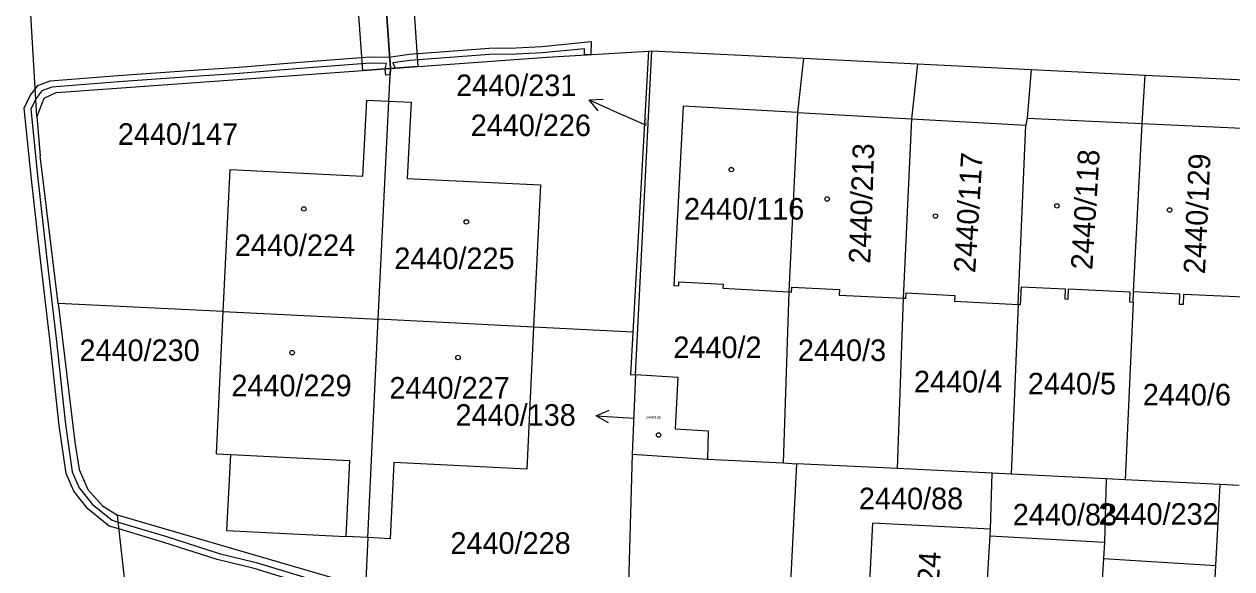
# Model space of a CAD drawing. Extents: x -755819 to -753140, y -1169796 to -1166000.
# Drawn here: x -755355.4 to -755260.2, y -1168237.4 to -1168194.5 of the extents above; entities that cross this region are included whole.
import ezdxf

# ---------------------------------------------------------------- set-up
doc = ezdxf.new("R2010")
doc.units = 0
for name, color, linetype in [('Vrstva 1', 7, 'Continuous'), ('Vrstva 16', 7, 'Continuous'), ('Vrstva 18', 7, 'Continuous'), ('Vrstva 19', 7, 'Continuous'), ('Vrstva 25', 7, 'Continuous'), ('Vrstva 27', 7, 'Continuous'), ('Vrstva 4', 7, 'Continuous')]:
    doc.layers.add(name, color=color, linetype=linetype)

msp = doc.modelspace()

# ---------------------------------------------------------------- linework, layer by layer
at = {"layer": 'Vrstva 1'}
for p, q in [((-755354.43, -1168201.81), (-755355.26, -1168187.16)), ((-755326.53, -1168198.02), (-755314.2, -1168197.14)), ((-755314.2, -1168197.14), (-755306.2, -1168196.65)), ((-755306.2, -1168196.65), (-755307.42, -1168218.8)), ((-755307.23, -1168222.13), (-755305.92, -1168196.63)), ((-755306.2, -1168196.65), (-755305.92, -1168196.63)), ((-755305.92, -1168196.63), (-755293.96, -1168197.22)), ((-755352.88, -1168199.91), (-755326.53, -1168198.02)), ((-755326.66, -1168200.6), (-755326.53, -1168198.02)), ((-755293.96, -1168197.22), (-755294.44, -1168201.49)), ((-755293.96, -1168197.22), (-755284.98, -1168197.66)), ((-755284.98, -1168197.66), (-755285.45, -1168201.99)), ((-755284.98, -1168197.66), (-755276.01, -1168198.1)), ((-755276.01, -1168198.1), (-755276.35, -1168201.93)), ((-755276.01, -1168198.1), (-755267.04, -1168198.54)), ((-755267.26, -1168202.36), (-755267.04, -1168198.54)), ((-755267.04, -1168198.54), (-755258.07, -1168198.98)), ((-755352.88, -1168199.91), (-755353.87, -1168200.38)), ((-755353.87, -1168200.38), (-755354.43, -1168201.81)), ((-755328.71, -1168206.5), (-755328.41, -1168200.51)), ((-755328.41, -1168200.51), (-755326.66, -1168200.6)), ((-755327.51, -1168217.78), (-755326.66, -1168200.6)), ((-755326.66, -1168200.6), (-755324.91, -1168200.69)), ((-755324.91, -1168200.69), (-755325.21, -1168206.68)), ((-755354.43, -1168201.81), (-755354.16, -1168204.91)), ((-755303.45, -1168200.99), (-755304.19, -1168215.13)), ((-755294.44, -1168201.49), (-755303.45, -1168200.99)), ((-755294.44, -1168201.49), (-755295.12, -1168215.63)), ((-755276.35, -1168201.93), (-755276.45, -1168202.48)), ((-755285.45, -1168201.99), (-755286.11, -1168216.12)), ((-755277.06, -1168216.62), (-755276.45, -1168202.48)), ((-755267.95, -1168215.63), (-755267.26, -1168202.36)), ((-755352.75, -1168216.54), (-755354.16, -1168204.91)), ((-755339.72, -1168217.18), (-755339.19, -1168205.98)), ((-755339.19, -1168205.98), (-755328.71, -1168206.5)), ((-755325.21, -1168206.68), (-755314.72, -1168207.2)), ((-755314.72, -1168207.2), (-755315.26, -1168218.4)), ((-755304.19, -1168215.13), (-755303.81, -1168215.15)), ((-755303.81, -1168215.15), (-755303.79, -1168214.82)), ((-755303.79, -1168214.82), (-755300.3, -1168215.01)), ((-755300.3, -1168215.01), (-755300.32, -1168215.34)), ((-755294.92, -1168215.64), (-755294.9, -1168215.24)), ((-755294.9, -1168215.24), (-755291.13, -1168215.43)), ((-755276.86, -1168216.63), (-755276.79, -1168215.22)), ((-755276.79, -1168215.22), (-755273.33, -1168215.39)), ((-755300.32, -1168215.34), (-755295.12, -1168215.63)), ((-755295.12, -1168215.63), (-755295.58, -1168229.08)), ((-755295.12, -1168215.63), (-755294.92, -1168215.64)), ((-755291.13, -1168215.43), (-755291.15, -1168215.88)), ((-755291.15, -1168215.88), (-755286.11, -1168216.12)), ((-755286.11, -1168216.12), (-755286.59, -1168229.53)), ((-755286.11, -1168216.12), (-755285.91, -1168216.13)), ((-755285.91, -1168216.13), (-755285.89, -1168215.69)), ((-755285.89, -1168215.69), (-755282.04, -1168215.9)), ((-755282.04, -1168215.9), (-755282.06, -1168216.35)), ((-755273.33, -1168215.39), (-755273.37, -1168216.18)), ((-755273.37, -1168216.18), (-755273.11, -1168216.19)), ((-755273.11, -1168216.19), (-755273.07, -1168215.39)), ((-755273.07, -1168215.39), (-755268.24, -1168215.62)), ((-755268.24, -1168215.62), (-755268.28, -1168216.42)), ((-755267.99, -1168216.43), (-755267.95, -1168215.63)), ((-755264.29, -1168215.81), (-755267.95, -1168215.63)), ((-755264.32, -1168216.61), (-755264.29, -1168215.81)), ((-755264.01, -1168215.82), (-755264.04, -1168216.62)), ((-755259.23, -1168216.05), (-755264.01, -1168215.82)), ((-755339.72, -1168217.18), (-755352.75, -1168216.54)), ((-755352.75, -1168216.54), (-755351.43, -1168227.46)), ((-755282.06, -1168216.35), (-755277.06, -1168216.62)), ((-755277.06, -1168216.62), (-755277.6, -1168229.98)), ((-755277.06, -1168216.62), (-755276.86, -1168216.63)), ((-755267.99, -1168216.43), (-755268.61, -1168230.43)), ((-755268.28, -1168216.42), (-755267.99, -1168216.43)), ((-755264.04, -1168216.62), (-755264.32, -1168216.61)), ((-755340.26, -1168228.38), (-755339.72, -1168217.18)), ((-755339.72, -1168217.18), (-755327.51, -1168217.78)), ((-755328.32, -1168234.98), (-755327.51, -1168217.78)), ((-755315.26, -1168218.4), (-755327.51, -1168217.78)), ((-755315.26, -1168218.4), (-755315.79, -1168229.6)), ((-755307.42, -1168218.8), (-755315.26, -1168218.4)), ((-755307.42, -1168218.8), (-755307.6, -1168222.16)), ((-755307.6, -1168222.16), (-755307.23, -1168222.13)), ((-755307.23, -1168222.13), (-755307.48, -1168228.42)), ((-755307.23, -1168222.13), (-755303.87, -1168222.33)), ((-755303.87, -1168222.33), (-755304.08, -1168226.42)), ((-755304.08, -1168226.42), (-755301.48, -1168226.56)), ((-755301.48, -1168226.56), (-755301.53, -1168228.79)), ((-755351.43, -1168227.46), (-755351.08, -1168229.61)), ((-755340.26, -1168228.38), (-755339.16, -1168228.43)), ((-755339.16, -1168228.43), (-755339.46, -1168234.43)), ((-755307.48, -1168228.42), (-755307.94, -1168244.9)), ((-755307.48, -1168228.42), (-755301.53, -1168228.79)), ((-755326.27, -1168229.07), (-755326.57, -1168235.07)), ((-755315.79, -1168229.6), (-755326.27, -1168229.07)), ((-755301.53, -1168228.79), (-755295.58, -1168229.08)), ((-755295.58, -1168229.08), (-755294.53, -1168229.17)), ((-755294.53, -1168229.17), (-755295.49, -1168248.57)), ((-755286.59, -1168229.53), (-755294.53, -1168229.17)), ((-755279.1, -1168229.9), (-755286.59, -1168229.53)), ((-755351.08, -1168229.61), (-755350.39, -1168231.19)), ((-755279.23, -1168234.31), (-755279.1, -1168229.9)), ((-755277.6, -1168229.98), (-755279.1, -1168229.9)), ((-755270.11, -1168230.35), (-755277.6, -1168229.98)), ((-755270.11, -1168230.35), (-755270.23, -1168235.33)), ((-755268.61, -1168230.43), (-755270.11, -1168230.35)), ((-755261.12, -1168230.8), (-755268.61, -1168230.43)), ((-755350.39, -1168231.19), (-755349.25, -1168232.47)), ((-755261.46, -1168237.18), (-755261.12, -1168230.8)), ((-755259.62, -1168230.87), (-755261.12, -1168230.8)), ((-755349.25, -1168232.47), (-755348.07, -1168233.2)), ((-755328.5, -1168238.9), (-755348.07, -1168233.2)), ((-755346.65, -1168245.86), (-755348.07, -1168233.2)), ((-755288.54, -1168233.84), (-755289.18, -1168246.38)), ((-755279.23, -1168234.31), (-755288.54, -1168233.84)), ((-755339.46, -1168234.43), (-755330.07, -1168234.89)), ((-755328.32, -1168234.98), (-755330.07, -1168234.89)), ((-755328.32, -1168234.98), (-755328.5, -1168238.9)), ((-755326.57, -1168235.07), (-755328.32, -1168234.98)), ((-755280.05, -1168247.85), (-755279.26, -1168234.83)), ((-755279.26, -1168234.83), (-755279.23, -1168234.31)), ((-755270.23, -1168235.33), (-755270.31, -1168236.63)), ((-755270.31, -1168236.63), (-755271.08, -1168248.47)), ((-755270.31, -1168236.63), (-755261.46, -1168237.18)), ((-755261.51, -1168238.17), (-755261.46, -1168237.18))]:
    msp.add_line(p, q, dxfattribs=at)
at = {"layer": 'Vrstva 16'}
for p, q in [((-755310.881, -1168200.5), (-755308.14, -1168201.72)), ((-755306.36, -1168202.52), (-755308.14, -1168201.72)), ((-755310.314, -1168225.378), (-755307.32, -1168225.56))]:
    msp.add_line(p, q, dxfattribs=at)
for points in [[(-755310.17, -1168201.363), (-755310.881, -1168200.5), (-755309.764, -1168200.45)], [(-755309.347, -1168225.938), (-755310.314, -1168225.378), (-755309.286, -1168224.939)]]:
    msp.add_lwpolyline(points, dxfattribs=at)
at = {"layer": 'Vrstva 25'}
for centre in [(-755299.66, -1168205.99), (-755292.11, -1168208.31), (-755333.37, -1168209.09), (-755283.57, -1168209.65), (-755273.99, -1168208.85), (-755265.1, -1168209.17), (-755320.56, -1168210.11), (-755334.29, -1168220.41), (-755321.21, -1168220.79), (-755305.4, -1168226.9)]:
    msp.add_circle(centre, 0.175, dxfattribs=at)
at = {"layer": 'Vrstva 27'}
for p, q in [((-755328.73, -1168198.18), (-755329.51, -1168187.22)), ((-755326.53, -1168198.02), (-755327.31, -1168187.06)), ((-755327.31, -1168187.06), (-755326.53, -1168198.02)), ((-755325.15, -1168186.9), (-755324.37, -1168197.87)), ((-755314.61, -1168196.29), (-755310.71, -1168195.91)), ((-755310.71, -1168195.91), (-755310.73, -1168196.93)), ((-755334.01, -1168197.56), (-755328.16, -1168197.11)), ((-755328.16, -1168197.11), (-755326.66, -1168197.13)), ((-755326.66, -1168197.13), (-755325.06, -1168196.9)), ((-755325.06, -1168196.9), (-755318.75, -1168196.43)), ((-755318.73, -1168196.93), (-755325, -1168197.4)), ((-755318.75, -1168196.43), (-755316.64, -1168196.39)), ((-755316.62, -1168196.89), (-755318.73, -1168196.93)), ((-755316.64, -1168196.39), (-755314.61, -1168196.29)), ((-755314.57, -1168196.79), (-755316.62, -1168196.89)), ((-755311.23, -1168196.47), (-755314.57, -1168196.79)), ((-755311.23, -1168196.96), (-755311.23, -1168196.47)), ((-755310.73, -1168196.93), (-755311.23, -1168196.96)), ((-755342.45, -1168198.18), (-755338.49, -1168197.91)), ((-755338.49, -1168197.91), (-755334.01, -1168197.56)), ((-755333.97, -1168198.06), (-755338.45, -1168198.41)), ((-755328.14, -1168197.61), (-755333.97, -1168198.06)), ((-755326.53, -1168198.02), (-755328.73, -1168198.18)), ((-755326.86, -1168197.63), (-755328.14, -1168197.61)), ((-755326.95, -1168198.05), (-755326.86, -1168197.63)), ((-755326.16, -1168197.99), (-755326.95, -1168198.05)), ((-755326.95, -1168198.05), (-755326.53, -1168198.02)), ((-755326.91, -1168198.55), (-755326.95, -1168198.05)), ((-755326.53, -1168198.02), (-755326.56, -1168198.52)), ((-755324.37, -1168197.87), (-755326.53, -1168198.02)), ((-755325, -1168197.4), (-755326.36, -1168197.59)), ((-755326.36, -1168197.59), (-755326.16, -1168197.99)), ((-755354.33, -1168199.37), (-755353.36, -1168198.99)), ((-755353.36, -1168198.99), (-755348.02, -1168198.59)), ((-755348.02, -1168198.59), (-755342.45, -1168198.18)), ((-755342.41, -1168198.68), (-755347.98, -1168199.09)), ((-755338.45, -1168198.41), (-755342.41, -1168198.68)), ((-755326.56, -1168198.52), (-755326.91, -1168198.55)), ((-755354.95, -1168200.15), (-755354.55, -1168199.65)), ((-755354.55, -1168199.65), (-755354.33, -1168199.37)), ((-755354.03, -1168199.79), (-755354.51, -1168200.41)), ((-755353.24, -1168199.49), (-755354.03, -1168199.79)), ((-755347.98, -1168199.09), (-755353.24, -1168199.49)), ((-755355.42, -1168201.14), (-755354.95, -1168200.15)), ((-755354.51, -1168200.41), (-755354.9, -1168201.22)), ((-755354.86, -1168206.51), (-755355.42, -1168201.14)), ((-755354.9, -1168201.22), (-755354.36, -1168206.45)), ((-755354.15, -1168212.87), (-755354.86, -1168206.51)), ((-755354.36, -1168206.45), (-755353.65, -1168212.81)), ((-755353.4, -1168219.35), (-755354.15, -1168212.87)), ((-755353.65, -1168212.81), (-755352.9, -1168219.29)), ((-755352.65, -1168226.14), (-755353.4, -1168219.35)), ((-755352.9, -1168219.29), (-755352.15, -1168226.08)), ((-755352.12, -1168229.94), (-755352.65, -1168226.14)), ((-755352.15, -1168226.08), (-755351.64, -1168229.8)), ((-755351.49, -1168231.33), (-755352.12, -1168229.94)), ((-755351.64, -1168229.8), (-755351.07, -1168231.07)), ((-755350.39, -1168232.72), (-755351.49, -1168231.33)), ((-755351.07, -1168231.07), (-755350.03, -1168232.36)), ((-755350.03, -1168232.36), (-755348.49, -1168233.61)), ((-755348.73, -1168234.07), (-755350.39, -1168232.72)), ((-755347.95, -1168234.3), (-755348.73, -1168234.07)), ((-755348.49, -1168233.61), (-755348.01, -1168233.76)), ((-755348.01, -1168233.76), (-755344.28, -1168234.88)), ((-755344.42, -1168235.36), (-755347.95, -1168234.3)), ((-755344.28, -1168234.88), (-755340.05, -1168236.22)), ((-755340.19, -1168236.7), (-755344.42, -1168235.36)), ((-755337.28, -1168237.41), (-755340.19, -1168236.7)), ((-755340.05, -1168236.22), (-755337.14, -1168236.93)), ((-755337.14, -1168236.93), (-755330.46, -1168238.97)), ((-755330.6, -1168239.45), (-755337.28, -1168237.41))]:
    msp.add_line(p, q, dxfattribs=at)
at = {"layer": 'Vrstva 4'}
for p, q in [((-755294.44, -1168201.49), (-755285.45, -1168201.99)), ((-755276.35, -1168201.93), (-755267.26, -1168202.36)), ((-755285.45, -1168201.99), (-755276.45, -1168202.48)), ((-755267.26, -1168202.36), (-755258.27, -1168202.78)), ((-755339.16, -1168228.43), (-755329.77, -1168228.9)), ((-755329.77, -1168228.9), (-755330.07, -1168234.89)), ((-755279.26, -1168234.83), (-755270.23, -1168235.33))]:
    msp.add_line(p, q, dxfattribs=at)

# ---------------------------------------------------------------- texts
at = {"layer": 'Vrstva 16'}
for s, p in [('2440/231', (-755321.362, -1168200.2)), ('2440/138', (-755321.408, -1168226.17))]:
    msp.add_text(s, height=1.7, dxfattribs=at).set_placement(p)
at = {"layer": 'Vrstva 18'}
for s, p in [('2440/226', (-755320.212, -1168203.35)), ('2440/147', (-755348.03, -1168204.04)), ('2440/2', (-755304.233, -1168220.84)), ('2440/230', (-755351.058, -1168221.07)), ('2440/3', (-755294.413, -1168221.07)), ('2440/4', (-755285.263, -1168223.54)), ('2440/5', (-755276.283, -1168223.7)), ('2440/6', (-755267.223, -1168224.57)), ('2440/88', (-755289.603, -1168232.75)), ('2440/83', (-755277.472, -1168234.02)), ('2440/232', (-755270.719, -1168233.97)), ('2440/228', (-755321.81, -1168236.26))]:
    msp.add_text(s, height=1.7, dxfattribs=at).set_placement(p)
msp.add_text('2440/231', height=0.1, rotation=87.14688, dxfattribs=at).set_placement((-755306.359, -1168202.506))
at = {"layer": 'Vrstva 19'}
for s, rotation, p in [('2440/213', 88.00632, (-755288.712, -1168213.423)), ('2440/117', 86.40204, (-755280.435, -1168214.163)), ('2440/118', 86.40204, (-755271.205, -1168213.923)), ('2440/129', 87.31877, (-755262.319, -1168214.243)), ('2440/124', 86.40204, (-755283.735, -1168245.603))]:
    msp.add_text(s, height=1.7, rotation=rotation, dxfattribs=at).set_placement(p)
for s, height, p in [('2440/116', 1.7, (-755303.393, -1168209.93)), ('2440/224', 1.7, (-755338.812, -1168212.8)), ('2440/225', 1.7, (-755326.234, -1168213.83)), ('2440/229', 1.7, (-755339.082, -1168223.85)), ('2440/227', 1.7, (-755326.617, -1168224.03)), ('2440/138', 0.2, (-755306.392, -1168225.61))]:
    msp.add_text(s, height=height, dxfattribs=at).set_placement(p)

doc.saveas('drawing.dxf')
